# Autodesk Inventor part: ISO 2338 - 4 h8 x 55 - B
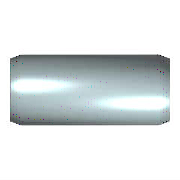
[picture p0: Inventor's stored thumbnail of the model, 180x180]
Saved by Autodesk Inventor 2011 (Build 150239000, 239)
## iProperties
IsCustomPart: 0
Created: 2009-02
Part Number: ISO 2338 - 4 h8 x 55 - B
Material: Stainless Steel, Austenitic
Description: Parallel Pin
Document SubType Name: Modeling
Standard: ISO 2338
Designer: 904Chiaki
Standards Organization: ISO
Language: en-US
Size Designation: 4 h8 x 55 - B
Categories: <MemberInstance><Categories><Category DisplayName="Fasteners" InternalName="e4da775c-781d-43d5-af7c-5136215cf5a6" Mnemonic="FSTN"><Category DisplayName="Pins" I
Density: 8.03 g/cm^3
Mass: 5.53951 g
Surface Area: 7.12086 cm^2
Volume: 0.689852 cm^3
Author: 904Chiaki
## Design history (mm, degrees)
sketch "Sketch"
  geometry: C1 r 2 at (0, 0); 1 further point
  constraints: 1 centre point, 1 coincident
  dimensions: "d1" = 4 diameter of C1 (= NND)
extrude "Body" new body sketch "Sketch" distance "d2" = 55 (= NLG); taper "d3" = 0 deg
chamfer "Sketch2" distance "d8" = 0.63 (= PHH); stored, may be unused: angle "d9" = 15 deg (= FAWI), second distance "d12" = 0.63 (= PHH)
body "Solid1"
chamfer "Chamfer1" distance "d4" = 0.63 (= PHH); stored, may be unused: angle "d5" = 15 deg (= FAWI), second distance "d11" = 0.63 (= PHH)
other parameters: "NND" = 4 [user parameter; used in 1 equation term], "NLG" = 55 [user parameter; used in 1 equation term], "PHH" = 0.63 [user parameter; used in 4 equation terms], "FAWI" = 15 deg [user parameter; used in 2 equation terms], "d13" = 0, "d15" = 0, "d16" = 0, "KAH" = 0 [user parameter]
